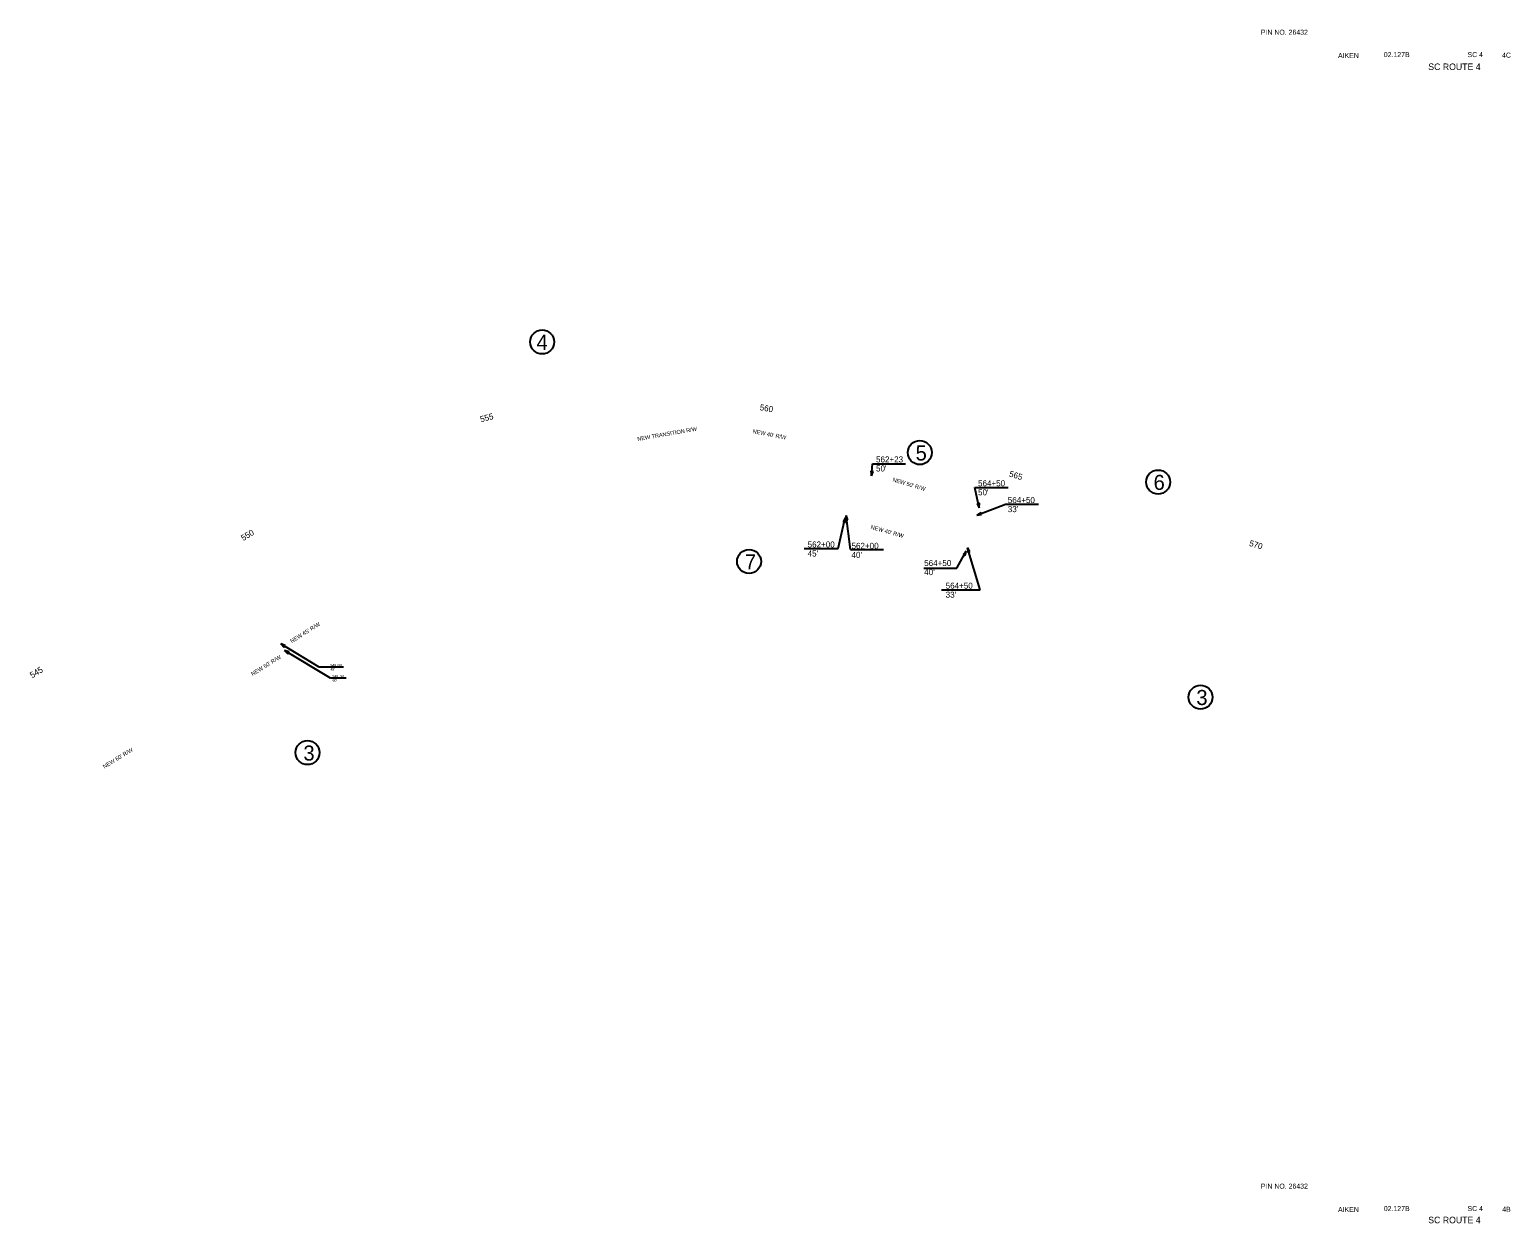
# Model space of a CAD drawing. Extents: x -64038 to -60892, y 1838 to 8465.
# Drawn here: x -63844 to -60893, y 6087 to 8465 of the extents above; entities that cross this region are included whole.
import ezdxf

# ---------------------------------------------------------------- set-up
doc = ezdxf.new("R2010")
doc.units = 0
for name, color, linetype in [('Level 1', 7, 'Continuous'), ('Level 13', 7, 'Continuous'), ('Level 21', 7, 'Continuous'), ('Level 24', 7, 'Continuous'), ('Level 25', 7, 'Continuous'), ('Level 33', 7, 'Continuous')]:
    doc.layers.add(name, color=color, linetype=linetype)

msp = doc.modelspace()

# ---------------------------------------------------------------- linework, layer by layer
at = {"layer": 'Level 24'}
for p, q in [((-62162.8, 7584.6), (-62167.3, 7584.9)), ((-62167.3, 7584.9), (-62165.8, 7575.8)), ((-62165.8, 7575.8), (-62162.8, 7584.6)), ((-62216.7, 7497), (-62217.7, 7487.8)), ((-62213.3, 7488.4), (-62216.7, 7497)), ((-61948.2, 7502.9), (-61955.8, 7497.6)), ((-61948.2, 7502.9), (-61955.8, 7497.6)), ((-61955.8, 7497.6), (-61946.6, 7498.7)), ((-61955.8, 7497.6), (-61946.6, 7498.7)), ((-61951, 7521.5), (-61955.4, 7520.6)), ((-61955.4, 7520.6), (-61951.4, 7512.3)), ((-61951.4, 7512.3), (-61951, 7521.5)), ((-61946.6, 7498.7), (-61948.2, 7502.9)), ((-61946.6, 7498.7), (-61948.2, 7502.9)), ((-62218.1, 7492.2), (-62222.3, 7484)), ((-62222.3, 7484), (-62217.9, 7482.9)), ((-62217.9, 7482.9), (-62218.1, 7492.2)), ((-62217.7, 7487.8), (-62213.3, 7488.4)), ((-61977, 7426), (-61983.3, 7419.2)), ((-61983.3, 7419.2), (-61979.3, 7417)), ((-61979.3, 7417), (-61977, 7426)), ((-61974.6, 7432.6), (-61974.2, 7423.3)), ((-61969.9, 7424.6), (-61974.6, 7432.6)), ((-61974.2, 7423.3), (-61969.9, 7424.6)), ((-63343.2, 7241), (-63336.7, 7234.4)), ((-63334.4, 7238.2), (-63343.2, 7241)), ((-63336.7, 7234.4), (-63334.4, 7238.2)), ((-63335.4, 7228.2), (-63328.8, 7221.6)), ((-63326.5, 7225.5), (-63335.4, 7228.2)), ((-63328.8, 7221.6), (-63326.5, 7225.5))]:
    msp.add_line(p, q, dxfattribs=at)
at = {"layer": 'Level 25'}
for centre in [(-62822.2, 7842.5), (-62069.7, 7622.2), (-61594.8, 7563.6), (-62409.9, 7405.4), (-61510.2, 7135.1), (-63289.7, 7024.6)]:
    msp.add_circle(centre, 23.9, dxfattribs=at)
at = {"layer": 'Level 33'}
for p, q in [((-62165.8, 7575.8), (-62164, 7599.8)), ((-62164, 7599.8), (-62098, 7599.8)), ((-61959.8, 7552.5), (-61893.8, 7552.5)), ((-61951.4, 7512.3), (-61959.8, 7552.5)), ((-62207.7, 7429.1), (-62216.7, 7497)), ((-61955.8, 7497.6), (-61898.7, 7519.5)), ((-61898.7, 7519.5), (-61832.8, 7519.5)), ((-62232.3, 7431.3), (-62218.1, 7492.2)), ((-62300.3, 7431.3), (-62232.3, 7431.3)), ((-62207.7, 7429.1), (-62141.7, 7429.1)), ((-61995.7, 7392), (-61977, 7426)), ((-61949.1, 7348.7), (-61974.6, 7432.6)), ((-62061.6, 7392), (-61995.7, 7392)), ((-62026.3, 7348.7), (-61949.1, 7348.7)), ((-63266.8, 7194.6), (-63343.2, 7241)), ((-63243.9, 7172.8), (-63335.4, 7228.2)), ((-63218.2, 7194.6), (-63266.8, 7194.6)), ((-63213, 7172.8), (-63243.9, 7172.8))]:
    msp.add_line(p, q, dxfattribs=at)

# ---------------------------------------------------------------- texts
at = {"layer": 'Level 1'}
for s, p in [('PIN NO. 26432', (-61389.9, 8454.5)), ('AIKEN', (-61236.2, 8408)), ('02.127B', (-61145, 8409.9)), ('SC 4', (-60978.2, 8409.9)), ('4C', (-60909.4, 8408.8)), ('PIN NO. 26432', (-61389.9, 6156.1)), ('AIKEN', (-61236.2, 6109.6)), ('02.127B', (-61145, 6111.5)), ('SC 4', (-60978.2, 6111.5)), ('4B', (-60909.1, 6110.1))]:
    msp.add_text(s, height=10, dxfattribs=at).set_placement(p)
at = {"layer": 'Level 13'}
for p in [(-61056.4, 8384.2), (-61056.4, 6087.2)]:
    msp.add_text('SC ROUTE 4', height=13, dxfattribs=at).set_placement(p)
at = {"layer": 'Level 21'}
for s, rotation, p in [('560', 349.8036, (-62389.4, 7706.9)), ('555', 14.8036, (-62944.1, 7682.5)), ('565', 343.4944, (-61892.7, 7574.8)), ('550', 31.6333, (-63417.7, 7445.7)), ('570', 343.4944, (-61414.3, 7436.7)), ('545', 31.6333, (-63838.4, 7172.5))]:
    msp.add_text(s, height=12, rotation=rotation, dxfattribs=at).set_placement(p)
at = {"layer": 'Level 25'}
for s, p in [('4', (-62833.4, 7826.8)), ('5', (-62078, 7606.4)), ('6', (-61603.8, 7547.9)), ('7', (-62418.2, 7389.7)), ('3', (-61518.5, 7119.4)), ('3', (-63297.9, 7008.8))]:
    msp.add_text(s, height=30, dxfattribs=at).set_placement(p)
at = {"layer": 'Level 33'}
for s, rotation, p in [('NEW TRANSITION R/W', 9.8615, (-62631.8, 7645.2)), ("NEW 40' R/W", 348.7635, (-62403.3, 7661.1)), ("NEW 50' R/W", 343.3735, (-62124.6, 7565)), ("NEW 40' R/W", 344.0506, (-62168.2, 7470.6)), ("NEW 45' R/W", 32.0859, (-63321.1, 7242.4)), ("NEW 60' R/W", 31.6334, (-63399.2, 7177.1)), ("NEW 60' R/W", 31.6334, (-63694.4, 6992.5))]:
    msp.add_text(s, height=8, rotation=rotation, dxfattribs=at).set_placement(p)
for s, height, p in [('562+23', 12, (-62156.9, 7602.6)), ("50'", 12, (-62156.9, 7584.6)), ('564+50', 12, (-61953.6, 7555.1)), ("50'", 12, (-61953.6, 7537.1)), ('564+50', 12, (-61894.3, 7521.6)), ("33'", 12, (-61894.3, 7503.6)), ('562+00', 12, (-62293.2, 7433.2)), ('562+00', 12, (-62205.7, 7430.5)), ("45'", 12, (-62293.2, 7415.2)), ("40'", 12, (-62205.7, 7412.5)), ('564+50', 12, (-62060.9, 7396.2)), ("40'", 12, (-62060.9, 7378.2)), ('564+50', 12, (-62018.1, 7351.2)), ("33'", 12, (-62018.1, 7333.2)), ('549+50', 5, (-63244.1, 7196)), ("45'", 5, (-63244.1, 7188)), ('549+50', 5, (-63239.9, 7174.2)), ("60'", 5, (-63239.9, 7166.2))]:
    msp.add_text(s, height=height, dxfattribs=at).set_placement(p)

doc.saveas('drawing.dxf')
